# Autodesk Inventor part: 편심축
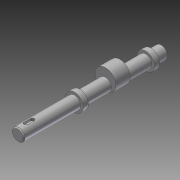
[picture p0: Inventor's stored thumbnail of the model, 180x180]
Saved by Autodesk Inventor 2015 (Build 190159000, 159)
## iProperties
Created: 2016-02
Part Number: 편심축
Material: 강철, 연강
Document SubType Name: Modeling
Designer: mduedu
Density: 1 g/cm^3
Appearance: 강철
Author: mduedu
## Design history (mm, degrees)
sketch "스케치1"
  geometry: C1 r 6 at (0, 0); 1 further point
  constraints: 1 centre point, 1 coincident
  dimensions: "d0" = 12 diameter of C1
extrude "돌출1" new body sketch "스케치1" distance "d1" = 140; taper "d2" = 0 deg
chamfer "모따기1" distance "d3" = 1; stored, may be unused: second distance "d4" = 2, angle "d5" = 45 deg
node "작업 평면1"
sketch "스케치2"
  geometry: C1 r 10 at (0, 4); C2 r 6 at (0, 0) reference; 1 further point
  constraints: 1 centre point, 1 tangent, 1 vertical alignment
  dimensions: "d7" = 20 diameter of C1
extrude "돌출2" join sketch "스케치2" stored distance "d8" = 14; taper "d9" = 0 deg
node "작업 평면2"
sketch "스케치3"
  geometry: C1 r 8.5 at (0, 0); 1 further point
  constraints: 1 centre point, 1 coincident
  dimensions: "d12" = 17 diameter of C1
extrude "돌출3" join sketch "스케치3" distance "d13" = 5; taper "d14" = 0 deg
node "작업 평면3"
sketch "스케치4"
  geometry: L1 (-5, 140)-(5, 140) reference; L2 (0, 140)-(0, 0); L3 (-2, 132)-(-2, 126); L4 (2, 126)-(2, 132); A1 r 2 centre (0, 132) between (2, 132) and (-2, 132); A2 r 2 centre (0, 126) between (-2, 126) and (2, 126)
  constraints: 6 end point, 4 point on circle, 4 tangent, 2 centre point, 2 point on line, 1 midpoint, 1 parallel, 1 perpendicular
  dimensions: "d15" = 4 distance between parallel lines of L3 L4; "d17" = 6 distance edge to line of A1 L1; "d18" = 10 dimension on A2 A1
extrude "돌출4" cut sketch "스케치4" distance "d19" = 2.5; taper "d20" = 0 deg
sketch "스케치5"
  geometry: L1 (6, 55)-(6, 139) reference; L2 (-6, 55)-(-6, 139) reference; L3 (6, 115)-(-6, 115); L4 (-5, 140)-(5, 140) reference; L5 (6, 116.5)-(4.5, 115); L6 (6, 116.5)-(6, 115); L7 (4.5, 115)-(6, 115); 1 further point
  constraints: 8 end point, 4 point on line, 2 collinear, 1 perpendicular
  dimensions: "d21" = 25 distance between parallel lines of L3 L4; "d22" = 3 diameter of L5.start L3; "d24" = 45 deg angle of L3 L5
revolve "회전1" sketch "스케치5" stored, may be unused: angle "d25" = 90 deg
sketch "스케치6"
  geometry: L1 (6, 116.5)-(4.5, 115) reference; L2 (6, 113.5)-(4.5, 115) reference; 2 further points
  constraints: 1 coincident
node "작업 평면4"
sketch "스케치7"
  geometry: C1 r 8.5 at (0, -4); 1 further point
  constraints: 1 centre point, 1 coincident
  dimensions: "d27" = 17 diameter of C1
extrude "돌출5" join sketch "스케치7" distance "d29" = 5; taper "d30" = 0 deg
node "작업점1"
node "솔리드1"
other parameters: "d6" = -48, "d11" = -11
